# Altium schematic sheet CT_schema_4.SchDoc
size 294 x 169 mm
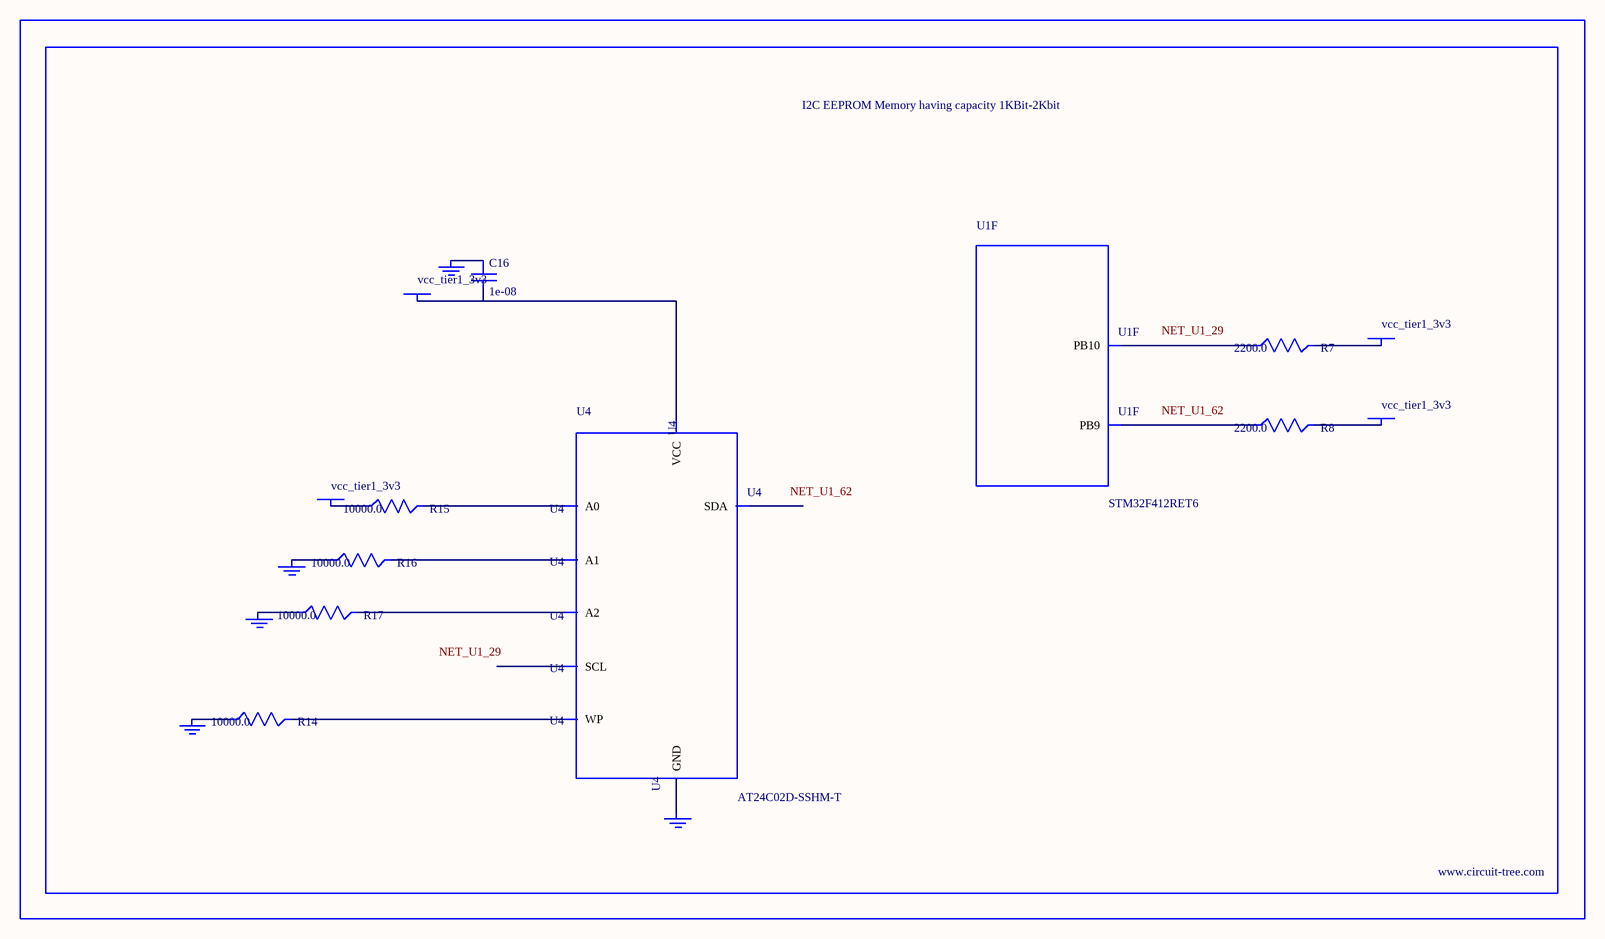
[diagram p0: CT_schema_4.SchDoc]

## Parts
BORDER3  (no value)
C16  1e-08  [C0402]
GND_INSTANCE_3_0  (no value)
GND_INSTANCE_3_1  (no value)
GND_INSTANCE_3_2  (no value)
GND_INSTANCE_3_3  (no value)
GND_INSTANCE_3_4  (no value)
POWER_INSTANCE_3_0  vcc_tier1_3v3
POWER_INSTANCE_3_1  vcc_tier1_3v3
POWER_INSTANCE_3_2  vcc_tier1_3v3
POWER_INSTANCE_3_3  vcc_tier1_3v3
R7  2200.0  [R0603]
R8  2200.0  [R0603]
R14  10000.0  [R0603]
R15  10000.0  [R0603]
R16  10000.0  [R0603]
R17  10000.0  [R0603]
U1  STM32F412RET6  [LQFP64]  (part F of 9)
U4  AT24C02D-SSHM-T  [AT24C02D]

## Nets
NetC16_1: C16.1 GND_INSTANCE_3_3.0(GND)
NetC16_2: C16.2 POWER_INSTANCE_3_1.0(PWR) U4.8(VCC)
NetGND_INSTANCE_3_0_0: GND_INSTANCE_3_0.0(GND) R16.1
NetGND_INSTANCE_3_1_0: GND_INSTANCE_3_1.0(GND) R17.1
NetGND_INSTANCE_3_2_0: GND_INSTANCE_3_2.0(GND) R14.1
NetGND_INSTANCE_3_4_0: GND_INSTANCE_3_4.0(GND) U4.4(GND)
NetPOWER_INSTANCE_3_0_0: POWER_INSTANCE_3_0.0(PWR) R15.1
NetPOWER_INSTANCE_3_2_0: POWER_INSTANCE_3_2.0(PWR) R7.2
NetPOWER_INSTANCE_3_3_0: POWER_INSTANCE_3_3.0(PWR) R8.2
NetR7_1: R7.1 U1.29(PB10)
NetR8_1: R8.1 U1.62(PB9)
NetR14_2: R14.2 U4.7(WP)
NetR15_2: R15.2 U4.1(A0)
NetR16_2: R16.2 U4.2(A1)
NetR17_2: R17.2 U4.3(A2)

Not connected (* = marked no-connect by the designer): U4 5(SDA) 6(SCL)

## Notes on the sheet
- Labels drawn without touching a wire or pin: NET_U1_29, NET_U1_62

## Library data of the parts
BORDER3 = BORDER_PAGE3
C16 = C0402C103K3RAC
GND_INSTANCE_3_0-GND_INSTANCE_3_4 = GND
POWER_INSTANCE_3_0-POWER_INSTANCE_3_3 = PWR
R7 R8 = RC0603JR-072K2L
R14-R17 = RC0603JR-0710KL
